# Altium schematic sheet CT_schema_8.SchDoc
size 274 x 160 mm
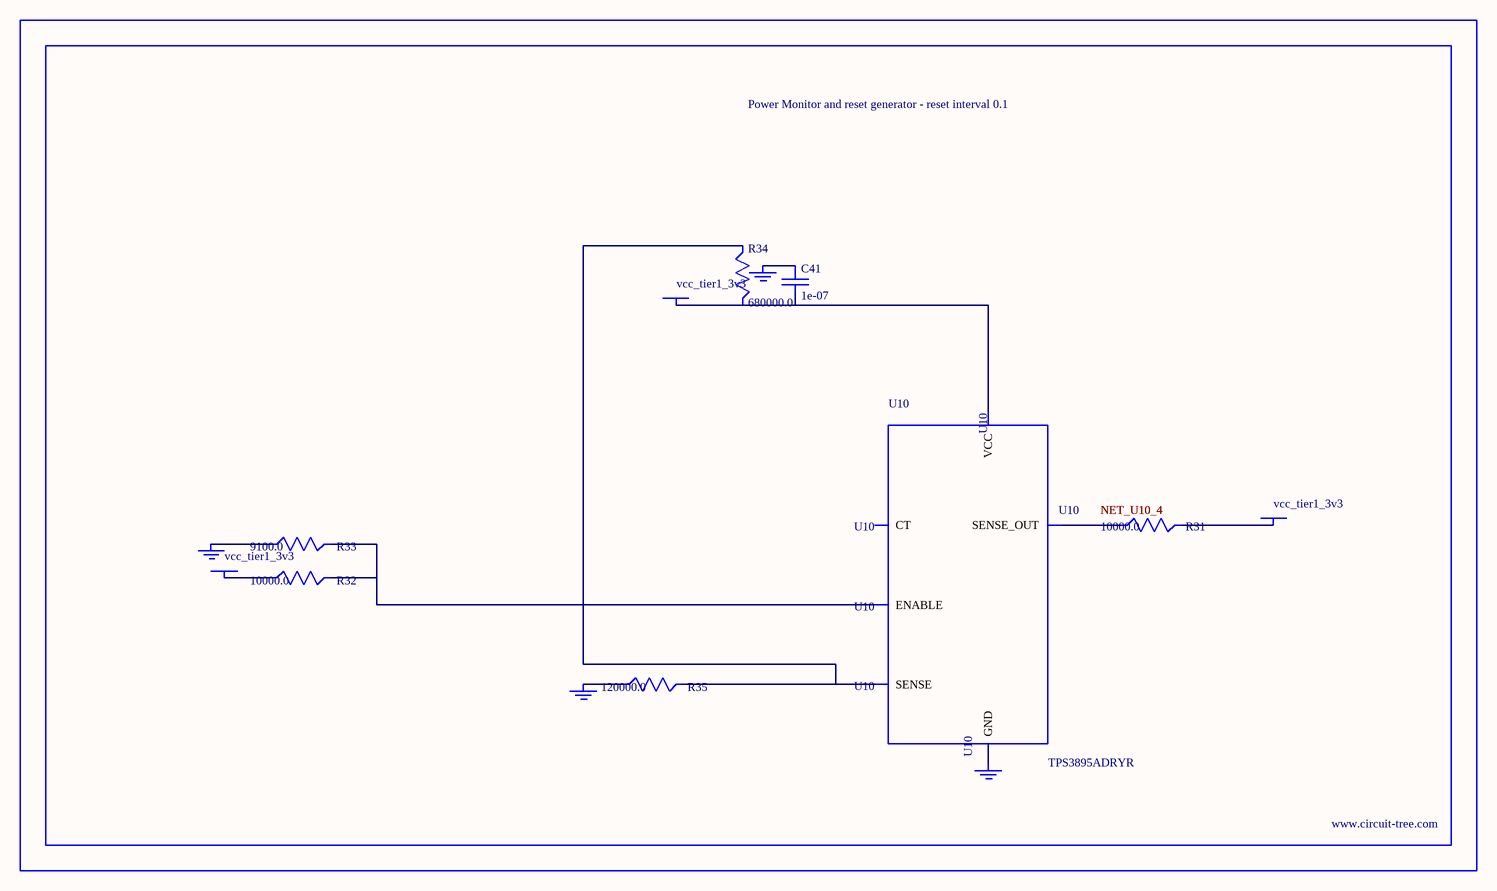
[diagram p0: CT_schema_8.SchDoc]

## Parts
BORDER7  (no value)
C41  1e-07  [C0402]
GND_INSTANCE_7_0  (no value)
GND_INSTANCE_7_1  (no value)
GND_INSTANCE_7_2  (no value)
GND_INSTANCE_7_3  (no value)
POWER_INSTANCE_7_0  vcc_tier1_3v3
POWER_INSTANCE_7_1  vcc_tier1_3v3
POWER_INSTANCE_7_2  vcc_tier1_3v3
R31  10000.0  [R0603]
R32  10000.0  [R0603]
R33  9100.0  [R0603]
R34  680000.0  [R0603]
R35  120000.0  [R0603]
U10  TPS3895ADRYR  [SON-6]

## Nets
NetC41_1: C41.1 GND_INSTANCE_7_2.0(GND)
NetC41_2: C41.2 POWER_INSTANCE_7_2.0(PWR) R34.2 U10.6(VCC)
NetGND_INSTANCE_7_0_0: GND_INSTANCE_7_0.0(GND) R33.1
NetGND_INSTANCE_7_1_0: GND_INSTANCE_7_1.0(GND) R35.1
NetGND_INSTANCE_7_3_0: GND_INSTANCE_7_3.0(GND) U10.2(GND)
NetPOWER_INSTANCE_7_0_0: POWER_INSTANCE_7_0.0(PWR) R32.1
NetPOWER_INSTANCE_7_1_0: POWER_INSTANCE_7_1.0(PWR) R31.2
NetR31_1: R31.1 U10.4(SENSE_OUT)
NetR32_2: R32.2 R33.2 U10.1(ENABLE)
NetR34_1: R34.1 R35.2 U10.3(SENSE)

Not connected (* = marked no-connect by the designer): U10 5(CT)

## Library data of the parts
BORDER7 = BORDER_PAGE7
C41 = C0402C104K3RACTU
GND_INSTANCE_7_0-GND_INSTANCE_7_3 = GND
POWER_INSTANCE_7_0-POWER_INSTANCE_7_2 = PWR
R31 R32 = RC0603JR-0710KL
R33 = RC0603JR-079K1L
R34 = RC0603JR-07680KL
R35 = RC0603JR-07120KL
